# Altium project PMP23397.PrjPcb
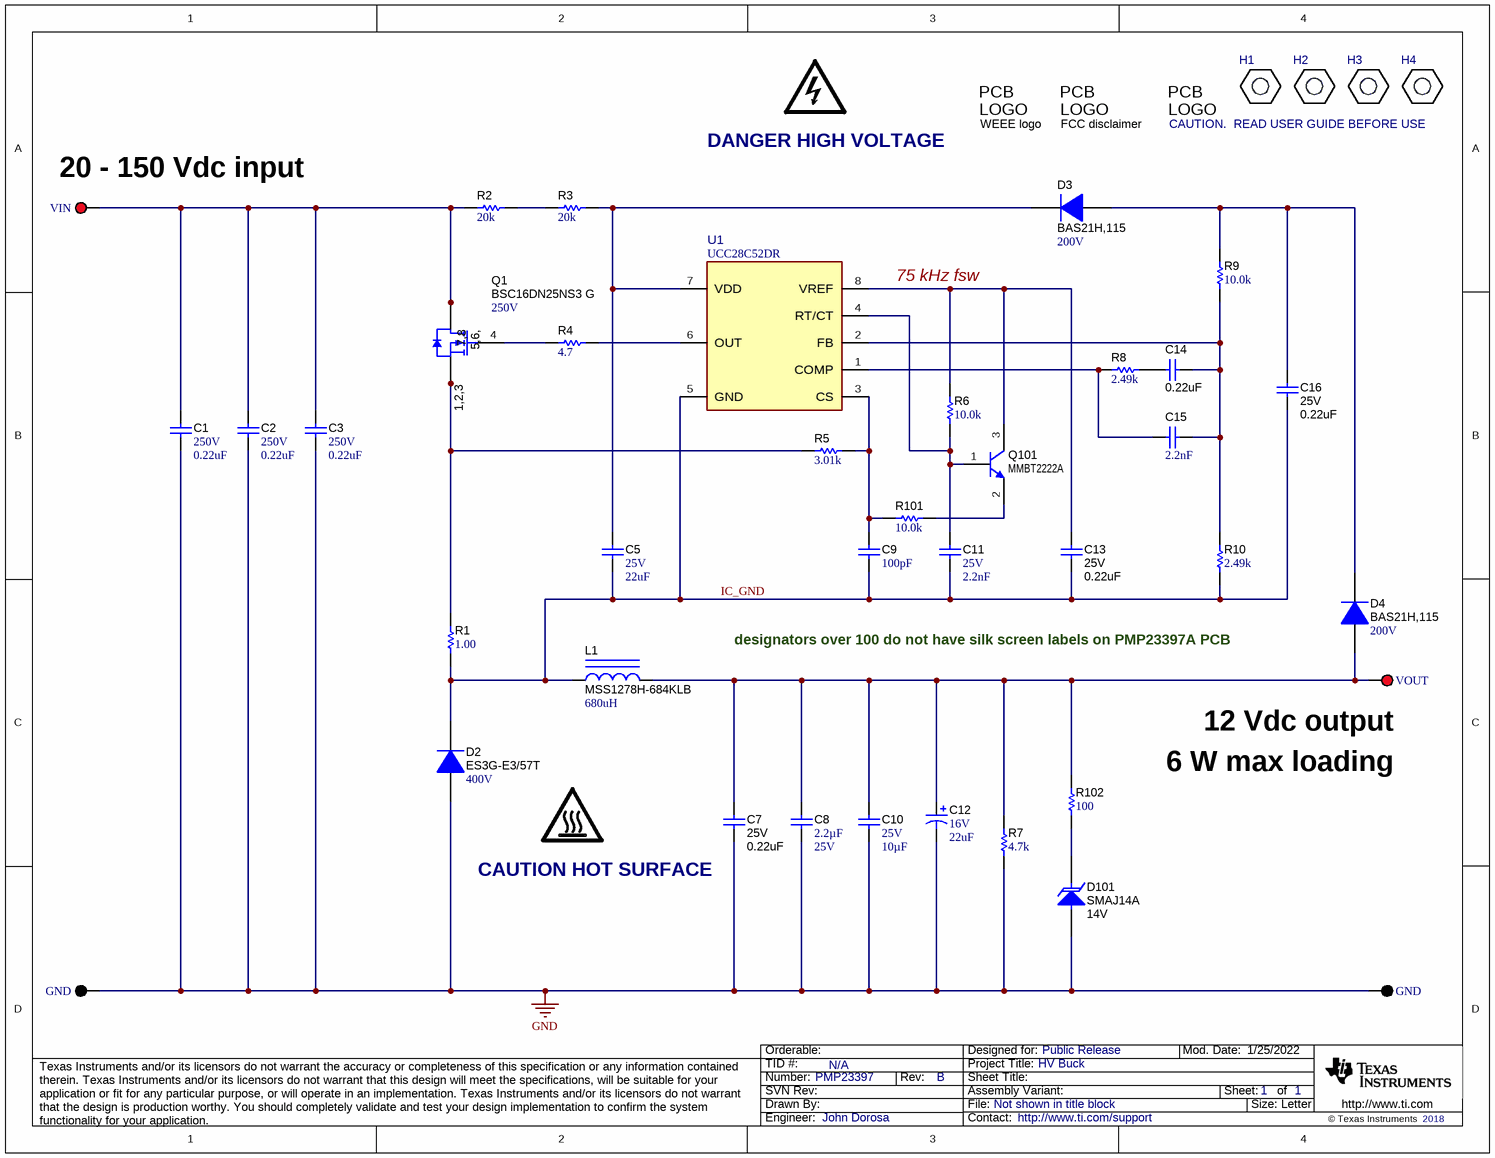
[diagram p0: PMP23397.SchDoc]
CopyrightYear: 2018; PCB_Layout: John Dorosa; PCB_Rev: B; PRJ_Customer: Public Release; PRJ_Engineer: John Dorosa; PRJ_Number: PMP23397; PRJ_Title: HV Buck; SCH_Rev: B; TechSupport: http://www.ti.com/support; TID: N/A
1 sheet, 47 parts. Net scope: global (net labels, ports and power ports of the same name join across sheets).
Board file: PMP23397.PcbDoc

## Sheet PMP23397.SchDoc
size Letter; Date: Not shown in title block; ApprovedBy: Not shown in title block; CheckedBy: Not shown in title block; Author: Not shown in title block; CompanyName: Not shown in title block; Engineer: Not shown in title block; Organization: Not shown in title block; Address1: Not shown in title block; Address2: Not shown in title block; Address3: Not shown in title block; Address4: Not shown in title block; DocumentNumber: 1; Revision: Use project parameter SCH_Rev; SheetNumber: 1; SheetTotal: 1; PageSetup: Record=PageOptions¦CenterHorizontal=True¦CenterVertical=True¦PrintScale=1.00¦XCorrection=1.00¦YCorrection=1.00¦PrintKind=0¦BorderSize=5000000¦LeftOffset=0¦BottomOffset=0¦Orientation=2¦PaperLength=1000¦PaperWidth=1000¦Scale=100¦PaperSource=15¦PrintQuality=600¦MediaType=1¦DitherType=10¦PaperKind=Letter¦PrintScaleMode=1

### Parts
(Parts that share a designator on the sheet are numbered #1, #2 ... from top to bottom, then left to right.)
C1  VDC_V: 250V  ValueDisplayed: 0.22uF  [1206]  (hidden comment: CGA5L3X7T2E224K160AE)
C2  VDC_V: 250V  ValueDisplayed: 0.22uF  [1206]  (hidden comment: CGA5L3X7T2E224K160AE)
C3  VDC_V: 250V  ValueDisplayed: 0.22uF  [1206]  (hidden comment: CGA5L3X7T2E224K160AE)
C5  VDC_V: 25V  ValueDisplayed: 22uF  [1210_270]  (hidden comment: GRM32ER61E226KE15L)
C7  Value2: 25V  ValueDisplayed: 0.22uF  [0603]  (hidden comment: GRM188R71E224KA88D)
C8  Cap_F: 2.2µF  VDC_V: 25V  [0805_HV]  (hidden comment: GRM21BR71E225KA73L)
C9  ValueDisplayed: 100pF  [0603]  (hidden comment: GRM1885C1H101JA01D)
C10  VDC_V: 25V  ValueDisplayed: 10µF  [1206]  (hidden comment: GRM31CR71E106MA12L)
C11  VDC_V: 25V  Cap_F: 2.2nF  [0603]  (hidden comment: GRM188R71E222KA01D)
C12  VDC_V: 16V  ValueDisplayed: 22uF  [SM_RADIAL_B]  (hidden comment: EEE-FK1C220UR)
C13  Value2: 25V  ValueDisplayed: 0.22uF  [0603]  (hidden comment: GRM188R71E224KA88D)
C14  ValueDisplayed: 0.22uF  [0603]  (hidden comment: GRM188R71E224KA88D)
C15  Cap_F: 2.2nF  [0603]  (hidden comment: GRM188R71E222KA01D)
C16  Value2: 25V  ValueDisplayed: 0.22uF  [0603]  (hidden comment: GRM188R71E224KA88D)
D2  ES3G-E3/57T  value 400V  [SMC]
D3  BAS21H,115  value 200V  [SOD-123F]
D4  BAS21H,115  value 200V  [SOD-123F]
D101  SMAJ14A  value 14V  [SMA]
GND#1  5011  [Keystone5011]  (value not drawn)
GND#2  5011  [Keystone5011]  (value not drawn)
H1  4824  [KEYSTONE_4824]  (value not drawn)
H2  4824  [KEYSTONE_4824]  (value not drawn)
H3  4824  [KEYSTONE_4824]  (value not drawn)
H4  4824  [KEYSTONE_4824]  (value not drawn)
L1  MSS1278H-684KLB  ValueDisplayed: 680uH  [MSS1278]
LOGO1  CAUTION HOT SURFACE  [IEC_HotSurface_Small]  (no BOM)
LOGO2  DANGER HIGH VOLTAGE  [IEC_HighVoltage_Small]  (no BOM)
Logo3  WEEE logo  [WEEE_Minimum]  (no BOM)
Logo4  FCC disclaimer  [FCC_disclaimer]  (no BOM)
Logo5  CAUTION.  READ USER GUIDE BEFORE USE  [IEC_Caution_Small]  (no BOM)
Q1  BSC16DN25NS3 G  value 250V  [PG-TDSON-8]
Q101  MMBT2222A  [SOT-23]
R1  ValueDisplayed: 1.00  [1206L]  (hidden comment: CRCW12061R00FKEA)
R2  ValueDisplayed: 20k  [1206L]  (hidden comment: CRCW120620K0JNEA)
R3  ValueDisplayed: 20k  [1206L]  (hidden comment: CRCW120620K0JNEA)
R4  ValueDisplayed: 4.7  [0603]  (hidden comment: CRCW06034R70JNEA)
R5  ValueDisplayed: 3.01k  [0603]  (hidden comment: CRCW06033K01FKEA)
R6  ValueDisplayed: 10.0k  [0603]  (hidden comment: CRCW060310K0FKEA)
R7  ValueDisplayed: 4.7k  [1206]  (hidden comment: CRCW12064K70JNEA)
R8  ValueDisplayed: 2.49k  [0603]  (hidden comment: CRCW06032K49FKEA)
R9  ValueDisplayed: 10.0k  [0603]  (hidden comment: CRCW060310K0FKEA)
R10  ValueDisplayed: 2.49k  [0603]  (hidden comment: CRCW06032K49FKEA)
R101  ValueDisplayed: 10.0k  [0603]  (hidden comment: CRCW060310K0FKEA)
R102  ValueDisplayed: 100  [1206]  (hidden comment: CRCW1206100RJNEA)
U1  UCC28C52DR  [D0008A-MFG]
VIN  5010  [Keystone5010]  (value not drawn)
VOUT  5010  [Keystone5010]  (value not drawn)

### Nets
GND: C1.2 C2.2 C3.2 C7.2 C8.2 C10.2 C12.2(-) D2.2(A) D101.2(A) GND#1.1 GND#2.1 R7.1
IC_GND: C5.2 C9.1 C11.2 C13.2 C16.1 D2.1(K) L1.1 R1.1 R10.1 U1.5(GND)
NetC1_1: C1.1 C2.1 C3.1 Q1.5(D) Q1.6(D) Q1.7(D) Q1.8(D) Q1.9(D) R2.1 VIN.1
NetC5_1: C5.1 D3.1(K) R3.2 U1.7(VDD)
NetC7_1: C7.1 C8.1 C10.1 C12.1(+) D4.2(A) L1.2 R7.2 R102.2 VOUT.1
NetC9_2: C9.2 R5.2 R101.2 U1.3(CS)
NetC11_1: C11.1 Q101.1(B) R6.1 U1.4(RT/CT)
NetC13_1: C13.1 Q101.3(C) R6.2 U1.8(VREF)
NetC14_1: C14.1 C15.2 R9.1 R10.2 U1.2(FB)
NetC14_2: C14.2 R8.2
NetC15_1: C15.1 R8.1 U1.1(COMP)
NetC16_2: C16.2 D3.2(A) D4.1(K) R9.2
NetD101_1: D101.1(K) R102.1
NetQ1_1: Q1.1(S) Q1.2(S) Q1.3(S) R1.2 R5.1
NetQ1_4: Q1.4(G) R4.1
NetQ101_2: Q101.2(E) R101.1
NetR2_2: R2.2 R3.1
NetR4_2: R4.2 U1.6(OUT)

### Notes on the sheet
- (near VIN) 20 - 150 Vdc input
- 75 kHz fsw
- designators over 100 do not have silk screen labels on PMP23397A PCB
- (near VOUT) 12 Vdc output
- 6 W max loading

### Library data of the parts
C1-C3 = CMP-0008793-2: CAP, CERM, 0.22 uF, 250 V, +/- 10%, X7T, AEC-Q200 Grade 1, 1206; Manufacturer: TDK; TaMin_C: -55°C; Polarized: N; SizeAreaWB_mm2: 10.92; Value1: Unknown; U/M: EA; Value: 0.22uF; TaMax_C: 125°C; SizeZ_mm: 1.35; SizeX_mm: 3.2; SizeY_mm: 1.6; SizeArea_mm2: 5.12; AEC Qualified: Y; Cap_F: 220nF; AEC Grade: 1; AEC Category: Q200
C5 = CMP-0009213-2: CAP, CERM, 22 uF, 25 V, +/- 10%, X5R, 1210; Manufacturer: MuRata; TaMin_C: -55°C; ESR_ohm: 2m; Polarized: N; SizeAreaWB_mm2: 14.7; Value1: 0.002 ohm; U/M: EA; Value: 22uF; TaMax_C: 85°C; SizeZ_mm: 2.7; SizeX_mm: 3.2; SizeY_mm: 2.5; Cap_Case: 1210; SizeArea_mm2: 8; Cap_F: 22µF; IRMS_A: 3.67A; AEC Category: Q200
C7 C13 C16 = CMP-0007415-4: CAP, CERM, 0.22 uF, 25 V, +/- 10%, X7R, 0603; Manufacturer: MuRata; TaMin_C: -55°C; Polarized: N; SizeAreaWB_mm2: 4.68; Value1: Unknown; U/M: EA; Value: 0.22uF; TaMax_C: 125°C; SizeZ_mm: 1; SizeX_mm: 1.6; SizeY_mm: 0.8; SizeArea_mm2: 1.28; Cap_F: 220nF; AEC Category: Q200
C8 = CMP-0008342-2: CAP, CERM, 2.2 uF, 25 V, +/- 10%, X7R, 0805; Manufacturer: MuRata; TaMin_C: -55°C; ESR_ohm: 5m; Polarized: N; SizeAreaWB_mm2: 6.75; Value1: 0.005 ohm; U/M: EA; Value: 2.2uF; TaMax_C: 125°C; SizeZ_mm: 1.45; SizeX_mm: 2; SizeY_mm: 1.25; Cap_Case: 0805; SizeArea_mm2: 2.5; AEC Category: Q200
C9 = CMP-0007171-4: CAP, CERM, 100 pF, 50 V, +/- 5%, C0G/NP0, 0603; Manufacturer: MuRata; TaMin_C: -55°C; Polarized: N; SizeAreaWB_mm2: 4.68; Value1: Unknown; U/M: EA; Value: 100pF; TaMax_C: 125°C; SizeZ_mm: 1; SizeX_mm: 1.6; SizeY_mm: 0.8; Value2: 50V; SizeArea_mm2: 1.28; AEC Category: Q200
C10 = CMP-0082252-1: CAP, CERM, 10 µF, 25 V,+/- 20%, X7R, AEC-Q200 Grade 1, 1206; Manufacturer: MuRata; SizeAreaWB_mm2: 10.92; SizeArea_mm2: 5.12; AEC Qualified: Y; AEC Category: Q200; Value: 10uF; TaMax_C: 125°C; SizeZ_mm: 1.35; AEC Grade: 1; Polarized: N; TaMin_C: -55°C; SizeY_mm: 1.6; U/M: EA; SizeX_mm: 3.2
C11 = CMP-0007414-5: CAP, CERM, 2200 pF, 25 V, +/- 10%, X7R, 0603; Manufacturer: MuRata; Value: 2200pF; AEC Category: Q200; TaMax_C: 125°C; Value1: Unknown; SizeArea_mm2: 1.28; SizeY_mm: 0.8; SizeAreaWB_mm2: 4.68; MFG_Status: TI_Obsolete; Polarized: N; TaMin_C: -55°C; SizeX_mm: 1.6; SizeZ_mm: 1; U/M: EA
C12 = CMP-0010700-1: CAP, AL, 22 uF, 16 V, +/- 20%, 1.35 ohm, AEC-Q200 Grade 2, SMD; Manufacturer: Panasonic; TaMin_C: -55°C; ESR_ohm: 1.35; Polarized: Y; SizeAreaWB_mm2: 47.25; U/M: EA; Value: 22uF; TaMax_C: 105°C; SizeZ_mm: 5.4; SizeX_mm: 5.5; SizeY_mm: 4.3; Cap_Case: B; SizeArea_mm2: 23.65; CompType: Capacitor; Cap_F: 22µF; IRMS_A: 90mA; AEC Grade: 2; AEC Category: Q200
C14 = CMP-0007415-4: CAP, CERM, 0.22 uF, 25 V, +/- 10%, X7R, 0603; Manufacturer: MuRata; TaMin_C: -55°C; Polarized: N; SizeAreaWB_mm2: 4.68; Value1: Unknown; U/M: EA; Value: 0.22uF; TaMax_C: 125°C; SizeZ_mm: 1; SizeX_mm: 1.6; SizeY_mm: 0.8; Value2: 25V; SizeArea_mm2: 1.28; Cap_F: 220nF; AEC Category: Q200
C15 = CMP-0007414-5: CAP, CERM, 2200 pF, 25 V, +/- 10%, X7R, 0603; Manufacturer: MuRata; Value: 2200pF; AEC Category: Q200; TaMax_C: 125°C; Value1: Unknown; SizeArea_mm2: 1.28; SizeY_mm: 0.8; VDC_V: 25V; SizeAreaWB_mm2: 4.68; MFG_Status: TI_Obsolete; Polarized: N; TaMin_C: -55°C; SizeX_mm: 1.6; SizeZ_mm: 1; U/M: EA
D2 = CMP-0077028-2: Diode, Ultrafast, 400 V, 3 A, SMC; Manufacturer: Vishay-Semiconductor; Green_Lifecycle: Not Set; SizeAreaWB_mm2: 83.2686; SizeY_mm: 6.22; Value1: 3A; TJmax_C: 150°C; SizeZ_mm: 2.6; Green_REACh: Incomplete; Vf_V: 1.1V; SizeArea_mm2: 50.5686; SizeX_mm: 8.13; AEC Category: Q101
D3 D4 = CMP-0029179-2: Diode, Standard Recovery Rectifier, 200 V, 0.2 A, SOD-123F; Manufacturer: Nexperia; TJmax_C: 150°C; AEC Qualified: N; Value2: 1.25V; Value1: 0.2A; SizeArea_mm2: 5.6; SizeAreaWB_mm2: 11.7; AEC Category: Q101; SizeZ_mm: 1.1; SizeY_mm: 1.6; Io_A: 200mA; Green_Lifecycle: Not Set; SizeX_mm: 3.5; Green_REACh: Incomplete
D101 = CMP-0084951-1: Diode, TVS, Uni, 14 V, 23.2 Vc, 400 W, 17.2 A, SMA; Manufacturer: Littelfuse; SizeX_mm: 5.59; SizeY_mm: 2.92; Value1: 23.2V; SizeArea_mm2: 16.3228; SizeZ_mm: 2.87; Ipp: 17.2A; AEC Category: Q101; Vbr_Max: 17.2V; Ppk: 400W; RJA_CperW: 120; AEC Qualified: N; SizeAreaWB_mm2: 37.3428; Vbr_Min: 15.6V
GND#1 GND#2 = CMP-0055148-1: Test Point, Multipurpose, Black, TH; Manufacturer: Keystone; CNHeader: FALSE; Green_Lifecycle: Active; Green_REACh: Passed; ContactFinish: Silver; CT: TRUE
H1-H4 = CMP-0003690-1: Manufacturer: Keystone; CompType: Standoff
L1 = CMP-0061928-2: Inductor, Shielded Drum Core, Ferrite, 680 uH, 0.75 A, 1.04 ohm, SMD; Manufacturer: Coilcraft; PartNumber: MSS1278-684KLB; Isat: 1.38A @ 30% inductance drop; Irms: 0.75A @ 40C rise; Green_Lifecycle: Not Set; SizeAreaWB_mm2: 204.49; DCR_ohm: 1.04; Green_REACh: Incomplete; Value: 680uH; Imax_A: 750mA; SizeZ_mm: 8.05; SizeX_mm: 12.3; Value2: 0.75A; SizeArea_mm2: 151.29; Ind_H: 680µH; AEC Category: Q200
LOGO1 = CMP-0074837-1: IEC 61010-1 Hot Surface Warning; SymbolCreator: a0412235
LOGO2 = CMP-0074835-1: IEC 61010-1 High Voltage Warning; SymbolCreator: a0412235
Logo3 = CMP-0074769-1
Logo4 = CMP-0074847-1: FCC_disclaimer; Library Reference: Logo
Logo5 = CMP-0074836-1: IEC 61010-1 Caution Warning; SymbolCreator: a0412235; Lib Reference: IEC_Caution
Q1 = CMP-0001102-3: MOSFET, N-CH, 250 V, 10.9 A, PG-TDSON-8; Alternate Manufacturer: None; Manufacturer: Infineon Technologies; SizeZ_mm: 1.12; ChType: N; Value2: 8.6 nC; SizeX_mm: 5.99; SizeAreaWB_mm2: 55.131; SizeY_mm: 4.9; Vgs_V: 20V; QgTyp_nC: 8.6; SizeArea_mm2: 29.351; AEC Category: Q101; IdsMax_A: 10.9A; U/M: EA
Q101 = CMP-0000385-2: Transistor, NPN, 40 V, 0.15 A, SOT-23; Manufacturer: Fairchild Semiconductor; TaMax_C: 150°C; Value2: 300; Value1: 0.15 A; Vcesat1_V: 300mV; SizeX_mm: 2.5; SizeY_mm: 3; TaMin_C: -55°C; IcRated_A: 150mA; CompType: BJT; SizeZ_mm: 1.1; Value: 40 V; SizeArea_mm2: 7.5; NPN: 1; Vceo_V: 40V; PNP: 0; AEC Category: Q101; SizeAreaWB_mm2: 14; U/M: EA
R1 = CMP-0016745-3: RES, 1.00, 1%, 0.25 W, AEC-Q200 Grade 0, 1206; Manufacturer: Vishay-Dale; Power_W: 250mW; TempCo: 100 ppm/C; Value_Code: 1R00; Value: 1.00; EIA_Code: E96; Res_ohm: 1; SizeX_mm: 3.2; SizeY_mm: 1.6; SizeZ_mm: 1.35; Value2: 0.25W; SizeArea_mm2: 5.12; AEC Qualified: Y; VDC_V: 200V; AEC Category: Q200; AEC Grade: 0
R2 R3 = CMP-0018626-3: RES, 20 k, 5%, 0.25 W, AEC-Q200 Grade 0, 1206; Manufacturer: Vishay-Dale; Power_W: 250mW; TempCo: 200 ppm/C; Value_Code: 20k0; Value: 20k; EIA_Code: E24; SizeX_mm: 3.2; SizeY_mm: 1.6; SizeZ_mm: 1.35; Value2: 0.25W; SizeArea_mm2: 5.12; AEC Qualified: Y; VDC_V: 200V; AEC Category: Q200; AEC Grade: 0
R4 = CMP-0025821-4: RES, 4.7, 5%, 0.1 W, AEC-Q200 Grade 0, 0603; Manufacturer: Vishay-Dale; Power_W: 100mW; TempCo: 200 ppm/C; Value_Code: 4R70; Value: 4.7; EIA_Code: E24; SizeX_mm: 1.6; SizeY_mm: 0.8; SizeZ_mm: 1; Value2: 0.1W; SizeArea_mm2: 1.28; AEC Qualified: Y; VDC_V: 75V; AEC Category: Q200; AEC Grade: 0
R5 = CMP-0022371-4: RES, 3.01 k, 1%, 0.1 W, AEC-Q200 Grade 0, 0603; Manufacturer: Vishay-Dale; Power_W: 100mW; TempCo: 100 ppm/C; Value_Code: 3k01; Value: 3.01k; EIA_Code: E96; SizeX_mm: 1.6; SizeY_mm: 0.8; SizeZ_mm: 1; Value2: 0.1W; SizeArea_mm2: 1.28; AEC Qualified: Y; VDC_V: 75V; AEC Category: Q200; AEC Grade: 0
R6 R9 R101 = CMP-0021998-4: RES, 10.0 k, 1%, 0.1 W, AEC-Q200 Grade 0, 0603; Manufacturer: Vishay-Dale; Power_W: 100mW; TempCo: 100 ppm/C; Value_Code: 10k0; Value: 10.0k; EIA_Code: E96; Res_ohm: 10k; SizeX_mm: 1.6; SizeY_mm: 0.8; SizeZ_mm: 1; Value2: 0.1W; SizeArea_mm2: 1.28; AEC Qualified: Y; VDC_V: 75V; AEC Category: Q200; AEC Grade: 0
R7 = CMP-0018689-3: RES, 4.7 k, 5%, 0.25 W, AEC-Q200 Grade 0, 1206; Manufacturer: Vishay-Dale; Power_W: 250mW; TempCo: 200 ppm/C; Value_Code: 4k70; Value: 4.7k; EIA_Code: E24; SizeX_mm: 3.2; SizeY_mm: 1.6; SizeZ_mm: 1.35; Value2: 0.25W; SizeArea_mm2: 5.12; AEC Qualified: Y; VDC_V: 200V; AEC Category: Q200; AEC Grade: 0
R8 R10 = CMP-0022277-4: RES, 2.49 k, 1%, 0.1 W, AEC-Q200 Grade 0, 0603; Manufacturer: Vishay-Dale; Power_W: 100mW; TempCo: 100 ppm/C; Value_Code: 2k49; Value: 2.49k; EIA_Code: E96; SizeX_mm: 1.6; SizeY_mm: 0.8; SizeZ_mm: 1; Value2: 0.1W; SizeArea_mm2: 1.28; AEC Qualified: Y; VDC_V: 75V; AEC Category: Q200; AEC Grade: 0
R102 = CMP-0018575-3: RES, 100, 5%, 0.25 W, AEC-Q200 Grade 0, 1206; Manufacturer: Vishay-Dale; Power_W: 250mW; TempCo: 200 ppm/C; Value_Code: 100R; Value: 100; EIA_Code: E24; SizeX_mm: 3.2; SizeY_mm: 1.6; SizeZ_mm: 1.35; Value2: 0.25W; SizeArea_mm2: 5.12; AEC Qualified: Y; VDC_V: 200V; AEC Category: Q200; AEC Grade: 0
U1 = CMP-0033671-1: Buck, Boost, Flyback, Forward Converter, SEPIC Regulator Positive Output Step-Up, Step-Down, Step-Up/Step-Down DC-DC Controller IC 8-SOIC; Manufacturer: Texas Instruments; SizeZ_mm: 1.75mm; AEC Qualified: No; Max Duty Cycle: 100%; Max Supply Voltage: 28V; Nominal Supply Current: 1.3mA; Number Of Outputs: 1; Standoff Height: 0.11mm; Switching Frequency: 1MHz; Switching Topology: Boost,Buck,Flyback,Other; TJmax_C: +125°C
VIN VOUT = CMP-0055147-1: Test Point, Multipurpose, Red, TH; Manufacturer: Keystone; CNHeader: FALSE; Green_Lifecycle: Active; Green_REACh: Passed; ContactFinish: Silver; CT: TRUE

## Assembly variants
001: not fitted C7 C12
